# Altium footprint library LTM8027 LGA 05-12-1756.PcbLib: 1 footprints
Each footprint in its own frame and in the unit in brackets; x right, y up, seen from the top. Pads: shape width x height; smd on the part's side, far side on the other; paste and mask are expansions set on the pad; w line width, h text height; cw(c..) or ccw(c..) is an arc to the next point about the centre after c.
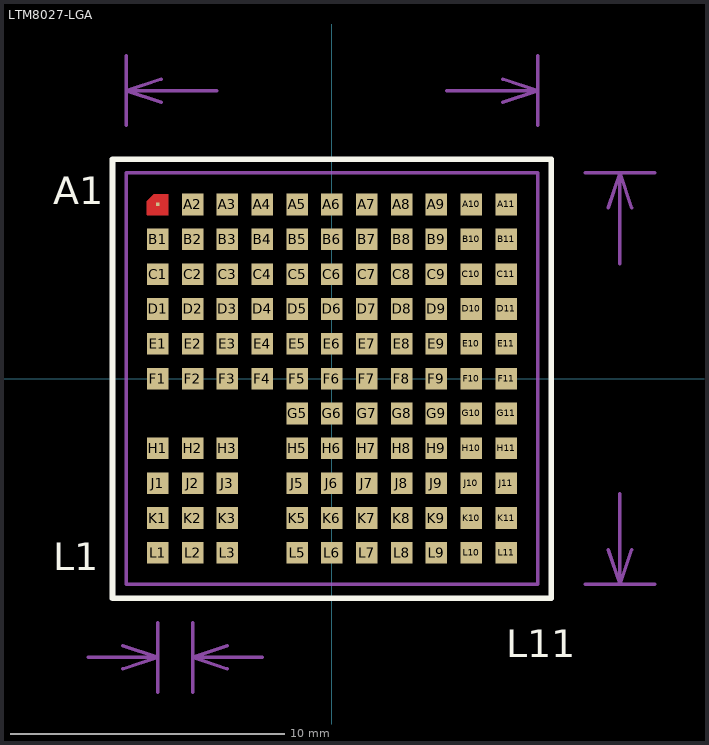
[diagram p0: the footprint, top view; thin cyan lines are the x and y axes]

## LTM8027-LGA [mil]
pads (113):
  rect 5x5 smd paste-3.5 mask-3: A1(-250,250)
  rect 31x31 smd paste-3.5 mask-3: A2(-200,250) A3(-150,250) A4(-100,250) A5(-50,250) A6(0,250) A7(50,250) A8(100,250) A9(150,250) A10(200,250) A11(250,250) B1(-250,200) B2(-200,200) B3(-150,200) B4(-100,200) B5(-50,200) B6(0,200) B7(50,200) B8(100,200) B9(150,200) B10(200,200) B11(250,200) C1(-250,150) C2(-200,150) C3(-150,150) C4(-100,150) C5(-50,150) C6(0,150) C7(50,150) C8(100,150) C9(150,150) C10(200,150) C11(250,150) D1(-250,100) D2(-200,100) D3(-150,100) D4(-100,100) D5(-50,100) D6(0,100) D7(50,100) D8(100,100) D9(150,100) D10(200,100) D11(250,100) E1(-250,50) E2(-200,50) E3(-150,50) E4(-100,50) E5(-50,50) E6(0,50) E7(50,50) E8(100,50) E9(150,50) E10(200,50) E11(250,50) F1(-250,0) F2(-200,0) F3(-150,0) F4(-100,0) F5(-50,0) F6(0,0) F7(50,0) F8(100,0) F9(150,0) F10(200,0) F11(250,0) G5(-50,-50) G6(0,-50) G7(50,-50) G8(100,-50) G9(150,-50) G10(200,-50) G11(250,-50) H1(-250,-100) H2(-200,-100) H3(-150,-100) H5(-50,-100) H6(0,-100) H7(50,-100) H8(100,-100) H9(150,-100) H10(200,-100) H11(250,-100) J1(-250,-150) J2(-200,-150) J3(-150,-150) J5(-50,-150) J6(0,-150) J7(50,-150) J8(100,-150) J9(150,-150) J10(200,-150) J11(250,-150) K1(-250,-200) K2(-200,-200) K3(-150,-200) K5(-50,-200) K6(0,-200) K7(50,-200) K8(100,-200) K9(150,-200) K10(200,-200) K11(250,-200) L1(-250,-250) L2(-200,-250) L3(-150,-250) L5(-50,-250) L6(0,-250) L7(50,-250) L8(100,-250) L9(150,-250) L10(200,-250) L11(250,-250)
TopLayer:
  region: -265,255 -255,265 -235,265 -235,235 -265,235
  lines w1: -265,235 -265,255 -255,265 -235,265 -235,235 -265,235
TopOverlay:
  lines w8: -314.96,-314.96 -314.96,314.96 314.96,314.96 314.96,-314.96 -314.96,-314.96
  text "L1" at -400,-275 h40
  text "A1" at -400,250 h40
  text "L11" at 250,-400 h40
Mechanical16:
  lines w5: -350,-400 -250,-400 ; -300,-416.67 -250,-400 ; -300,-383.33 -250,-400 ; -295.28,363.39 -295.28,463.39 ; -250,-450 -250,-350 ; -245.28,396.72 -295.28,413.39 ; -245.28,430.05 -295.28,413.39 ; -200,-450 -200,-350 ; -164.95,413.39 -295.28,413.39 ; -150,-416.67 -200,-400 ; -150,-383.33 -200,-400 ; -100,-400 -200,-400 ; 164.95,413.39 295.28,413.39 ; 245.28,396.72 295.28,413.39 ; 245.28,430.05 295.28,413.39 ; 295.28,363.39 295.28,463.39 ; 363.39,-295.28 463.39,-295.28 ; 363.39,295.28 463.39,295.28 ; 396.72,-245.28 413.39,-295.28 ; 396.72,245.28 413.39,295.28 ; 413.39,-164.95 413.39,-295.28 ; 413.39,164.95 413.39,295.28 ; 430.05,-245.28 413.39,-295.28 ; 430.05,245.28 413.39,295.28 ; -295.28,-295.28 295.28,-295.28 295.28,295.28 -295.28,295.28 -295.28,-295.28
  text "1.27 (mm)" at -425.77,-519.97 h50
  text "15 (mm)" at 443.38,-154.95 h50
  text "15 (mm)" at -154.95,383.39 h50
